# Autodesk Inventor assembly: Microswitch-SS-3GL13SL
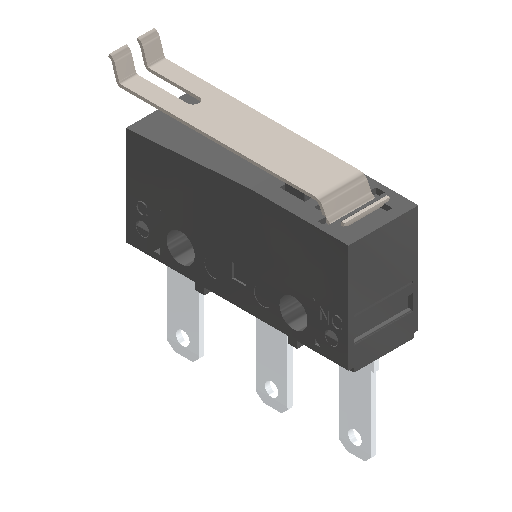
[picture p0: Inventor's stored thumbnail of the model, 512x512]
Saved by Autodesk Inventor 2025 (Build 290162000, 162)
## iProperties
Created: 2018-02
Part Number: Microswitch-SS-3GL13SL
Description: STEP AP214
Document SubType Name: Assembly
Designer: Ryzen5700u
Sending System: SolidWorks 2018
Preprocessor: SwSTEP 2.0
Title: Microswitch-SS-3GL13SL.STEP
Revision Number: ANY
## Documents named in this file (5)
- C:\Users\Ryzen5700u\Desktop\slider_2040\Microswitch-SS-3GL13SL\Microswitch-SS-3GL13SL.iam
- C:\Users\Ryzen5700u\Desktop\slider_2040\Microswitch-SS-3GL13SL\limit-switch-bottomcase.ipt
- C:\Users\Ryzen5700u\Desktop\slider_2040\Microswitch-SS-3GL13SL\limit-switch-top-case.ipt
- C:\Users\Ryzen5700u\Desktop\slider_2040\Microswitch-SS-3GL13SL\pins.ipt
- C:\Users\Ryzen5700u\Desktop\slider_2040\Microswitch-SS-3GL13SL\switch_lever.ipt
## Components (4 placed, 4 different names)
1. limit-switch-bottomcase_1
2. limit-switch-top-case_2 — Angolo:1, Coincidente:1
3. pins_3
4. switch_lever_4 — Angolo:1, Coincidente:1
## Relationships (2: Angle 1, Mate 1)
- Angolo:1 [Angle]: limit-switch-top-case_2 ↔ switch_lever_4
- Coincidente:1 [Mate]: limit-switch-top-case_2 ↔ switch_lever_4
